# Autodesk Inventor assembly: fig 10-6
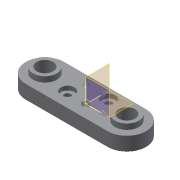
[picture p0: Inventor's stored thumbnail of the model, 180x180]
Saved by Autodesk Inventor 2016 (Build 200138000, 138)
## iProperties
Created: 2010-08
Part Number: fig 10-6
Document SubType Name: Assembly
Designer: CADSoft
Author: CADSoft
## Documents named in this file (2)
- D:\KAVITA\Autodesk Inventor_ 2016 Project_Kavita\Inventor_Part Files\Inventor_2016_Part\c10_Inv_2016\c10_inv_2016_prt\fig 10-6.iam
- D:\KAVITA\Autodesk Inventor_ 2016 Project_Kavita\Inventor_Part Files\Inventor_2016_Part\c10_Inv_2016\c10_inv_2016_prt\Part6.ipt
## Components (1 placed, 1 different names)
1. Part6:1
